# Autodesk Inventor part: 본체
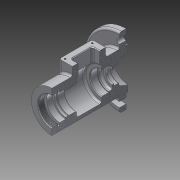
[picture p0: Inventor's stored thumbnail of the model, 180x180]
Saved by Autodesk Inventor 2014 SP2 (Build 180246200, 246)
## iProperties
Created: 2017-05
Part Number: 본체
Material: 알루미늄 6061
Document SubType Name: Modeling
Designer: 거성
Density: 2.71 g/cm^3
Appearance: 알루미늄 - 평지
Author: 거성
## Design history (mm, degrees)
sketch "스케치1"
  geometry: C1 r 31 at (0, 0); 1 further point
  constraints: 1 centre point, 1 coincident
  dimensions: "d0" = 62 diameter of C1
extrude "돌출1" new body sketch "스케치1" stored distance "d1" = 115; taper "d2" = 0 deg
node "작업 평면1"
sketch "스케치2"
  geometry: L1 (31, 57.5)-(-31, 57.5) reference; L2 (0, 57.5)-(0, -57.5); L3 (-31, -57.5)-(31, -57.5) reference; L4 (21, 57.5)-(21, 48.5); L5 (21, 48.5)-(24, 48.5); L6 (24, 48.5)-(24, 45.5); L7 (24, 45.5)-(20, 45.5); L8 (20, 45.5)-(20, 36.5); L9 (20, 36.5)-(17.5, 36.5); L10 (17.5, 36.5)-(17.5, 33.25); L11 (17.5, 33.25)-(18.5, 33.25); L12 (18.5, 33.25)-(18.5, 31.5); L13 (18.5, 31.5)-(17.5, 31.5); L14 (17.5, 31.5)-(17.5, 20.5); L15 (17.5, 20.5)-(23, 20.5); L16 (23, -17.5)-(17.5, -17.5); L17 (17.5, -17.5)-(17.5, -28.5); L18 (17.5, -28.5)-(16.5, -28.5); L19 (16.5, -28.5)-(16.5, -30.5); L20 (13.5, -33.5)-(10, -33.5); L21 (10, -33.5)-(10, -36.2); L22 (16.5, -43.5)-(22, -57.5); L23 (0, -57.5)-(22, -57.5); L24 (21, 57.5)-(0, 57.5); L25 (10, -36.2)-(12.2, -36.2); L26 (12.5, -36.5)-(12.5, -42.8); L27 (12.904, -43.5)-(16.5, -43.5); L28 (12.5, -42.8)-(12.904, -43.5); L29 (12.5, -42.8)-(16.75, -42.8); L30 (26, 17.5)-(26, -14.5); A1 r 0.3 centre (12.2, -36.5) between (12.5, -36.5) and (12.2, -36.2); A2 r 3 centre (13.5, -30.5) between (13.5, -33.5) and (16.5, -30.5); A3 r 3 centre (23, 17.5) between (26, 17.5) and (23, 20.5); A4 r 3 centre (23, -14.5) between (23, -17.5) and (26, -14.5); 7 further points
  constraints: 56 end point, 14 parallel, 10 point on line, 8 perpendicular, 8 point on circle, 8 tangent, 4 centre point, 3 collinear, 3 midpoint, 2 horizontal, 1 equal radius, 1 vertical, 4 other
  dimensions: "d22" = 60 deg angle of L28 L29; "d23" = 0.7 vertical distance of L26.end L27.start; "d32" = 12 vertical distance of L6.end L4.start; "d33" = 3 distance of L5.end L6.end; "d34" = 21 vertical distance of L4.start L8.end; "d35" = 26 vertical distance of L4.start L12.end; "d42" = 42 diameter of L4 L2; "d43" = 48 diameter of L6 L2; "d44" = 40 diameter of L8 L2; "d45" = 1.75 distance of L11.end L12.end; "d46" = 37 diameter of L12 L2; "d50" = 3 radius of A3; "d51" = 11 distance of L13.end L14.end; "d52" = 11 distance of L16.end L17.end; "d53" = 38 distance between parallel lines of L16 L15; "d55" = 52 diameter of L30 L2; "d56" = 5 vertical distance of L20.start L18.end; "d57" = 2.7 distance of L20.end L21.end; "d58" = 7.3 vertical distance of L27.start L25.end; "d59" = 14 vertical distance of L22.start L22.end; "d60" = 33 diameter of L22.start L2; "d61" = 44 diameter of L22.end L2; "d62" = 20 diameter of L21 L2; "d63" = 25 diameter of L26 L2; "d64" = 33 diameter of L19 L2; "d65" = 35 diameter of L17 L2; "d66" = 3 radius of A2; "d67" = 0.3 radius of A1; "d68" = 4.25045 distance of L26.end L29.end
revolve "회전1" sketch "스케치2" stored, may be unused: angle "d69" = 90 deg
node "작업 평면2"
node "작업 평면3"
node "작업 평면4"
sketch "스케치5"
  geometry: C1 r 31 at (0, 0) reference; C2 r 53 at (0, 0); 1 further point
  constraints: 1 centre point, 1 coincident
  dimensions: "d81" = 106 diameter of C2
extrude "돌출4" join sketch "스케치5" distance "d82" = 10; taper "d83" = 0 deg
feature "스레드1" dims "d90" = 10, "d91" = 0
fillet "모깎기3" dims "d95" = 3
node "작업 평면5"
sketch "스케치7"
  geometry: L1 (20, -23.5)-(-20, -23.5); L2 (-20, -23.5)-(-20, 26.5); L3 (-20, 26.5)-(20, 26.5); L4 (20, 26.5)-(20, -23.5); L5 (31, 57.5)-(-31, 57.5) reference; L6 (20, 1.5)-(-20, 1.5); 2 further points
  constraints: 10 end point, 3 midpoint, 2 parallel, 1 horizontal, 1 perpendicular, 1 vertical alignment
  dimensions: "d97" = 40 distance of L2.end L3.end; "d98" = 50 distance of L1.end L2.end; "d100" = 56 distance between parallel lines of L6 L5
extrude "돌출6" join sketch "스케치7" stored distance "d101" = 10; taper "d102" = 0 deg
sketch "스케치8"
  geometry: L1 (-15.5, 19)-(15.5, 19); L2 (15.5, 19)-(15.5, -22); L3 (15.5, -22)-(-15.5, -22); L4 (-15.5, -22)-(-15.5, 19); L5 (15.5, -1.5)-(-15.5, -1.5); L6 (-31, -57.5)-(31, -57.5) reference; L7 (-11, 14.5)-(11, 14.5); L8 (11, 14.5)-(11, -17.5); L9 (11, -17.5)-(-11, -17.5); L10 (-11, -17.5)-(-11, 14.5); L11 (11, -1.5)-(-11, -1.5); 4 further points
  constraints: 20 end point, 7 midpoint, 4 parallel, 2 horizontal, 2 perpendicular, 2 vertical alignment
  dimensions: "d103" = 31 distance of L2.end L3.end; "d104" = 41 distance of L3.end L1.start; "d105" = 56 distance between parallel lines of L6 L5; "d106" = 32 distance of L7.end L8.end; "d107" = 22 distance of L8.end L9.end; "d108" = 56 distance between parallel lines of L6 L11
extrude "돌출7" cut sketch "스케치8" stored distance "d109" = 30; taper "d110" = 0 deg
hole "구멍1" sketch "스케치8" diameter "d111" = 2.459; stored, may be unused: countersink angle "d115" = 90 deg, drill point angle "d117" = 118 deg; dims "d112" = 6, "d113" = 4, "d114" = 2, "d116" = 8
fillet "모깎기4" dims "d118" = 3
fillet "모깎기5" dims "d119" = 3
chamfer "모따기2" distance "d120" = 1; stored, may be unused: second distance "d121" = 2, angle "d122" = 45 deg
sketch "스케치9"
  geometry: C1 r 31 at (0, 0) reference; C2 r 53 at (0, 0) reference; A1 r 41.5 centre (0, 0) between (41.5, 0) and (0, 41.5); A2 r 4 centre (41.5, 0) between (37.5, 0) and (45.5, 0); A3 r 4 centre (0, 41.5) between (0, 37.5) and (0, 45.5); A4 r 4 centre (-41.5, 0) between (-37.5, 0) and (-45.5, 0); A5 r 4 centre (0, -41.5) between (0, -37.5) and (0, -45.5); A6 r 37.5 centre (0, 0) between (0, 37.5) and (-37.5, 0); A7 r 37.5 centre (0, 0) between (0, -37.5) and (37.5, 0); A8 r 45.5 centre (0, 0) between (0, 45.5) and (-45.5, 0); A9 r 45.5 centre (0, 0) between (0, -45.5) and (45.5, 0)
  constraints: 20 point on circle, 9 centre point, 2 horizontal alignment, 2 vertical alignment, 1 coincident
  dimensions: "d123" = 83 diameter of A1; "d124" = 8 diameter of A2; "d125" = 8 diameter of A3; "d126" = 8 diameter of A4; "d127" = 8 diameter of A5; "d128" = 37.5 radius of A7; "d129" = 45.5 radius of A9; "d130" = 37.5 radius of A6; "d131" = 45.5 radius of A8
extrude "돌출8" cut sketch "스케치9" distance "d132" = 10; taper "d133" = 0 deg
chamfer "모따기3" distance "d134" = 1; stored, may be unused: second distance "d135" = 2, angle "d136" = 45 deg
sketch "스케치10"
  geometry: L1 (44, 0)-(0, 0) reference; L2 (-34, -13)-(-34, -75) reference; 2 further points
  constraints: 1 other
  dimensions: "d137" = 56 distance from line of point (22, -8) L2; "d138" = 8 distance from line of point (22, -8) L1
feature "엠보싱1" sketch "스케치10" dims "d139" = 0.5, "d140" = 0
fillet "모깎기6" dims "d141" = 3
fillet "모깎기7" dims "d142" = 0.3
chamfer "모따기4" distance "d143" = 1; stored, may be unused: second distance "d144" = 2, angle "d145" = 45 deg
node "솔리드1"
other parameters: "d3" = 0, "d70" = -3, "d74" = 44, "d80" = -3, "d96" = 44
